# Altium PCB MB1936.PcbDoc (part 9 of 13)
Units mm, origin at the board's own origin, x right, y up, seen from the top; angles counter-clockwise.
Board outline 172 x 137 mm, 6 copper layers (Top Layer, Signal Layer 1, Signal Layer 2, Signal Layer 3, Signal Layer 4, Bottom Layer), stack 1.549 mm thick; 859 components, 672 nets, 3477 pads, 2222 vias.
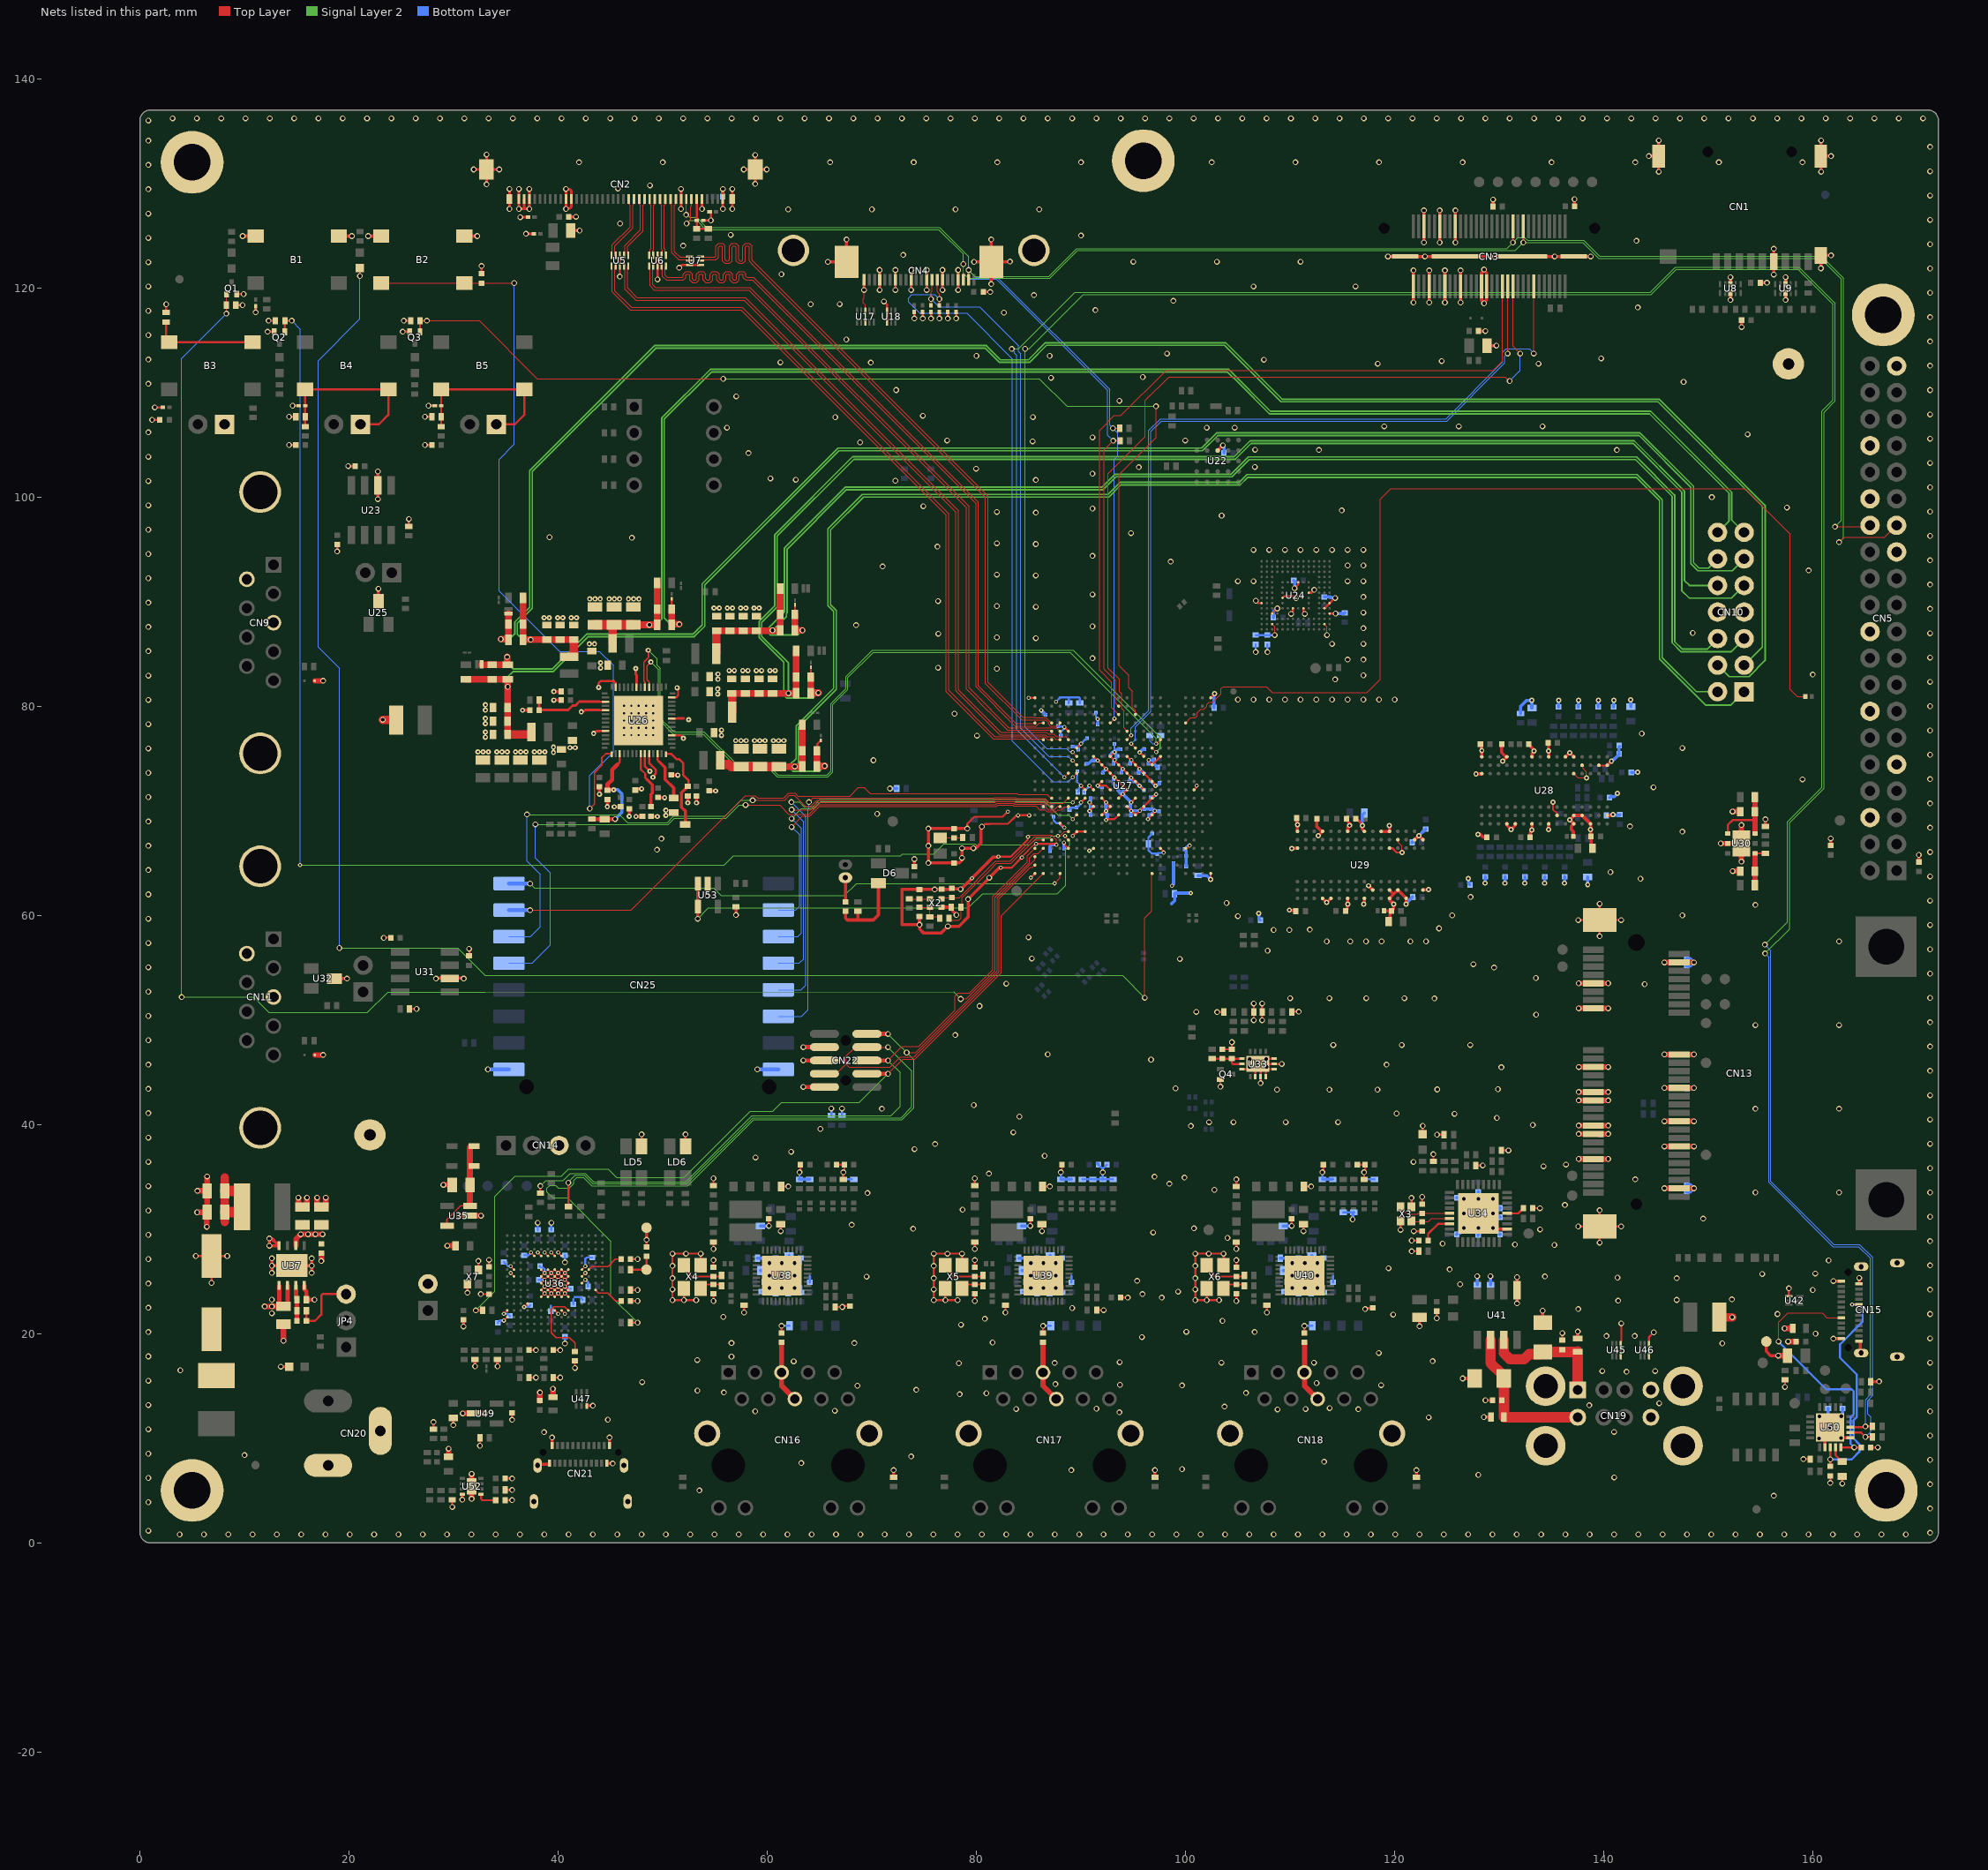
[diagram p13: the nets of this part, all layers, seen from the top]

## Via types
v1: diameter 0.55, hole 0.35, Top Layer to Bottom Layer, 1661 vias
v2: diameter 0.4, hole 0.2, Top Layer to Bottom Layer, tented both sides, 253 vias
v3: diameter 0.5, hole 0.2, Top Layer to Bottom Layer, 157 vias
v4: diameter 0.5, hole 0.25, Top Layer to Bottom Layer, 145 vias
v5: diameter 0.4, hole 0.2, Top Layer to Bottom Layer, 6 vias

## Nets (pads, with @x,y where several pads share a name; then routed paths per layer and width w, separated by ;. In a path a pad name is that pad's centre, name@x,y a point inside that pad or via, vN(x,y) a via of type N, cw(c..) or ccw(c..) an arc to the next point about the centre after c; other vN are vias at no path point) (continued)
GND: (continued)
  other v1: 3.8,0.8 6.125,0.8 8.45,0.8 10.775,0.8 13.1,0.8 15.425,0.8 17.75,0.8 20.075,0.8 22.4,0.8 24.725,0.8 27.05,0.8 29.375,0.8 31.7,0.8 34.025,0.8 36.35,0.8 38.675,0.8 41,0.8 43.325,0.8 45.65,0.8 47.975,0.8 50.3,0.8 52.625,0.8 54.95,0.8 57.275,0.8 59.6,0.8 61.925,0.8 64.25,0.8 66.575,0.8 68.9,0.8 71.225,0.8 73.55,0.8 75.875,0.8 78.2,0.8 80.525,0.8 82.85,0.8 85.175,0.8 87.5,0.8 89.825,0.8 92.15,0.8 94.475,0.8 96.8,0.8 99.125,0.8 101.45,0.8 103.775,0.8 106.1,0.8 108.425,0.8 110.75,0.8 113.075,0.8 115.4,0.8 117.725,0.8 120.05,0.8 122.375,0.8 124.7,0.8 127.025,0.8 129.35,0.8 131.675,0.8 134,0.8 136.325,0.8 138.65,0.8 140.975,0.8 143.3,0.8 145.625,0.8 147.95,0.8 150.275,0.8 152.6,0.8 154.925,0.8 157.25,0.8 159.575,0.8 161.9,0.8 164.225,0.8 166.55,0.8 168.875,0.8 171.2,0.95 0.8,1.15 171.2,3.275 0.8,3.875 156.25,4.5 53.5,5 171.2,5.6 0.8,6.2 141,6.25 128,6.5 89.075,6.95 99.66,7.05 63.25,7.625 113.25,7.75 171.2,7.925 73.75,8.25 10,8.375 0.8,8.525 160.587,9.988 171.2,10.25 38.65,10.58 140.975,10.6 0.8,10.85 44.75,11.775 123.25,12 160.612,12.087 93.675,12.475 58.85,12.575 171.2,12.575 66.45,12.625 108.8,12.75 116.525,12.775 83.8,12.8 111.475,12.8 91.475,12.825 113.775,12.875 103.725,13.025 138.6,13.15 0.8,13.175 145.3,13.35 78.4,14.2 80.95,14.3 105.775,14.325 55.85,14.375 53.325,14.55 74.25,14.625 171.2,14.9 68.625,15.025 99.66,15.05 118.7,15.075 93.725,15.1 87.55,15.175 112.525,15.275 48.03,15.376 0.8,15.5 142.175,16.35 139.85,16.425 144.9,16.425 3.875,16.5 78.325,17.175 87.475,17.2 103.425,17.225 112.275,17.225 171.2,17.225 93.7,17.275 62.525,17.35 123.625,17.375 53.3,17.475 56.575,17.8 0.8,17.825 118.475,18.15 151.325,19.075 56.575,19.1 68.325,19.1 81.55,19.15 171.2,19.55 95.825,19.675 140.25,19.775 142.95,19.775 160.25,20 0.8,20.15 106.6,20.15 100.075,20.175 78.525,20.85 103.525,21.225 80.8,21.425 55.8,21.6 119.85,21.825 156.6,21.875 171.2,21.875 137.55,22.35 89.15,22.45 0.8,22.475 141.375,23.15 146.975,23.225 152.25,23.275 97.725,23.45 95.875,23.775 99.275,24.025 159.975,24.175 171.2,24.2 61.4,24.35 62.6,24.35 86.4,24.35 87.6,24.35 111.4,24.35 112.6,24.35 126.25,24.725 0.8,24.8 95.375,25.05 146.975,25.3 141.3,25.35 69.5,25.45 134.375,25.475 60.2,25.55 61.4,25.55 62.6,25.55 85.2,25.55 86.4,25.55 87.6,25.55 110.2,25.55 111.4,25.55 112.6,25.55 155.15,25.7 160.225,25.75 125.25,26.15 119.4,26.25 171.2,26.525 60.2,26.75 61.4,26.75 62.6,26.75 85.2,26.75 86.4,26.75 87.6,26.75 110.2,26.75 111.4,26.75 112.6,26.75 161.5,27 0.8,27.125 135.275,28.475 131.5,28.525 124.575,28.6 171.2,28.85 104,29.15 0.8,29.45 96.9,29.675 133.9,29.975 73.95,30.025 100.8,30.075 68.075,30.4 149.5,31 171.2,31.175 126.6,31.5 128,31.5 0.8,31.775 78.675,31.85 136.275,32.3 129.4,32.9 69.575,33.45 154.5,33.5 162.5,33.5 171.2,33.5 102.75,33.75 0.8,34.1 98.45,34.325 143,34.75 99.9,34.925 97.025,35 81.2,35.3 171.2,35.825 134.225,36 136.375,36.175 0.8,36.425 121.8,36.425 58.875,36.85 86.525,37 62.275,37.4 74.075,37.65 76.05,38.125 171.2,38.15 0.8,38.75 83.525,39.25 65.075,39.575 100.5,39.85 133.2,39.95 102.25,40.225 104.575,40.225 109.575,40.225 114.575,40.225 171.2,40.475 129.775,40.625 84.1,40.75 125.725,41.025 120.175,41.05 0.8,41.075 70.95,41.5 154.5,41.5 162.5,41.5 79.75,41.85 171.2,42.8 108.75,43.325 113.75,43.325 118.35,43.325 124.075,43.35 129.875,43.375 0.8,43.4 99.044,43.453 171.2,45.125 59.04,45.265 130.2,45.475 106.125,45.49 107.75,45.49 0.8,45.725 119.225,45.725 106.925,45.815 96.7,46.2 106.125,46.24 107.725,46.265 86.825,46.7 171.2,47.45 114.125,47.6 120.675,47.6 127.225,47.6 0.8,48.05 77.975,48.55 154.5,49.5 162.5,49.5 171.2,49.775 0.8,50.375 133.525,50.5 101.03,50.765 80.3,51.325 123.8,52.05 110,52.075 113.75,52.075 117.275,52.075 120.925,52.075 171.2,52.1 0.8,52.7 143.909,53.412 82.85,53.475 28.315,53.95 30.965,53.95 133.5,54 171.2,54.425 129.5,55 0.8,55.025 127.525,55.325 99.45,55.825 85.3,55.875 107.85,56.625 171.2,56.75 31.475,56.795 0.8,57.35 113.5,57.5 115.75,57.5 117.25,57.5 118.75,57.5 121.5,57.5 123,57.5 162.5,57.5 23.315,57.845 84.975,57.9 108.427,58.602 109.927,58.602 111.875,58.625 124.25,58.75 171.2,59.075 0.8,59.675 105,59.925 125.5,60 147.5,60 154.5,61 103.925,61.175 171.2,61.4 127.25,61.75 0.8,62 143.5,63.5 171.2,63.725 140.625,64.125 0.8,64.325 171.2,66.05 49.45,66.275 0.8,66.65 49.875,67.325 147.5,68 171.2,68.375 142.5,68.5 0.8,68.975 70.5,69.7 171.2,70.7 0.8,71.3 144.75,72.25 159,73 171.2,73.025 0.8,73.625 70.15,74.825 171.2,75.35 0.8,75.95 147.5,76 80.05,77.175 143.625,77.375 171.2,77.675 0.8,78.275 77.9,79.275 171.2,80 0.8,80.6 105,80.625 106.5,80.625 108,80.625 109.5,80.625 111,80.625 112.5,80.625 114,80.625 115.5,80.625 117,80.625 118.5,80.625 120,80.625 171.2,82.325 114.3,82.55 0.8,82.925 117,82.95 159.975,83.025 81.95,83.575 76.325,83.675 115.5,84.45 117,84.45 91.1,84.575 171.2,84.65 0.8,85.25 114,85.95 117,85.95 85.675,86.5 81.95,86.575 76.35,86.925 171.2,86.975 148.5,87 117,87.45 0.8,87.575 91.1,87.625 68.5,87.75 117,88.95 171.2,89.3 85.675,89.5 81.95,89.575 0.8,89.9 76.325,90.05 117,90.45 91.1,90.675 171.2,91.625 105,91.95 106.5,91.95 115.5,91.95 117,91.95 0.8,92.225 85.675,92.5 81.95,92.575 159.587,92.982 71.025,93.35 115.5,93.45 117,93.45 98.575,93.825 171.2,93.95 91.1,94.375 0.8,94.55 106.5,94.95 108,94.95 109.5,94.95 111,94.95 112.5,94.95 114,94.95 115.5,94.95 117,94.95 76.275,95.25 85.675,95.5 81.95,95.575 47.05,96.1 39.175,96.15 171.2,96.275 94.775,96.55 0.8,96.875 103.45,98.225 85.675,98.5 81.95,98.575 171.2,98.6 114.936,98.709 91.1,98.9 157.5,99 74.925,99.125 0.8,99.2 150.325,99.975 171.2,100.925 0.8,101.525 72.25,101.55 85.675,101.625 62.725,101.65 60.3,101.775 91.1,102.225 79.975,102.7 95.525,102.85 106.625,102.875 171.2,103.25 0.8,103.85 58.2,104.2 112.75,104.5 141.25,104.5 106.65,104.525 68.875,105.225 85.375,105.325 77.2,105.4 99.975,105.4 171.2,105.575 91.1,105.7 153.75,106 0.8,106.175 56.15,106.625 102.025,106.625 104.7,106.625 119,106.75 126.125,106.75 134.125,106.75 66.5,107.625 85.4,107.65 74.875,107.775 171.2,107.9 93.675,109.2 57.025,109.625 72.325,110.225 171.2,110.225 0.8,110.825 147.625,111 87.125,111.4 95.9,111.475 171.2,112.55 118.375,112.75 133.75,112.75 69.9,112.85 61.25,112.875 124.5,113 107.5,113.125 0.8,113.15 139.75,113.25 80,113.5 87,113.5 98.225,113.725 171.2,114.875 67.55,115.05 0.8,115.475 171.2,117.2 82.625,117.625 0.8,117.8 91.375,117.875 143.25,118.125 64.15,118.425 66.925,118.45 98.825,118.75 85.501,119.298 171.2,119.525 0.8,120.125 106.5,120.125 116.25,120.125 81.425,120.355 61.35,121.3 171.2,121.85 0.8,122.45 83.2,122.505 95,122.5 103,122.5 111,122.5 73,123.15 51.95,124.025 171.2,124.175 143.125,124.5 81.415,124.625 0.8,124.775 90,125 56.5,125.075 45.925,126.15 171.2,126.5 0.8,127.1 62,127.5 70,127.5 78,127.5 86,127.5 171.2,128.825 0.8,129.425 45.725,129.5 48.775,129.8 171.2,131.15 0.8,131.75 42,132 50,132 66,132 74,132 82,132 90,132 102.5,132 110.5,132 118.5,132 126.5,132 135,132 143,132 151,132 159,132 171.2,133.475 0.8,134.075 0.8,136 3.125,136.2 5.45,136.2 7.775,136.2 10.1,136.2 12.425,136.2 14.75,136.2 17.075,136.2 19.4,136.2 21.725,136.2 24.05,136.2 26.375,136.2 28.7,136.2 31.025,136.2 33.35,136.2 35.675,136.2 38,136.2 40.325,136.2 42.65,136.2 44.975,136.2 47.3,136.2 49.625,136.2 51.95,136.2 54.275,136.2 56.6,136.2 58.925,136.2 61.25,136.2 63.575,136.2 65.9,136.2 68.225,136.2 70.55,136.2 72.875,136.2 75.2,136.2 77.525,136.2 79.85,136.2 82.175,136.2 84.5,136.2 86.825,136.2 89.15,136.2 91.475,136.2 93.8,136.2 96.125,136.2 98.45,136.2 100.775,136.2 103.1,136.2 105.425,136.2 107.75,136.2 110.075,136.2 112.4,136.2 114.725,136.2 117.05,136.2 119.375,136.2 121.7,136.2 124.025,136.2 126.35,136.2 128.675,136.2 131,136.2 133.325,136.2 135.65,136.2 137.975,136.2 140.3,136.2 142.625,136.2 144.95,136.2 147.275,136.2 149.6,136.2 151.925,136.2 154.25,136.2 156.575,136.2 158.9,136.2 161.225,136.2 163.55,136.2 165.875,136.2 168.2,136.2 170.525,136.2
  other v2: 95.6,75.575
  other v3: 46.8,69.467 50.3,69.552 50.3,70.052 44.7,70.382 43.95,71.587 39.55,75.577 32.324,75.625 32.825,75.625 33.326,75.625 34.124,75.625 34.625,75.625 35.126,75.625 35.924,75.625 36.425,75.625 36.926,75.625 37.724,75.625 38.225,75.625 38.726,75.625 41.124,76.029 41.625,76.029 39.55,76.077 56.979,76.702 57.48,76.702 57.981,76.702 58.779,76.702 59.28,76.702 59.781,76.702 60.579,76.702 61.08,76.702 61.581,76.702 33.05,77.027 55.62,77.202 46.3,77.227 47,77.227 47.7,77.227 48.4,77.227 49.1,77.227 33.05,77.527 55.62,77.702 46.3,77.927 47,77.927 47.7,77.927 48.4,77.927 49.1,77.927 33.05,78.327 46.3,78.627 47,78.627 47.7,78.627 48.4,78.627 49.1,78.627 52.48,78.702 33.05,78.827 46.3,79.327 47,79.327 47.7,79.327 48.4,79.327 49.1,79.327 33.05,79.627 46.3,80.027 47,80.027 47.7,80.027 48.4,80.027 49.1,80.027 33.05,80.127 55.25,81.152 55.25,81.652 55.275,82.577 55.275,83.077 56.35,83.402 56.85,83.402 57.65,83.402 58.15,83.402 58.95,83.402 59.45,83.402 60.25,83.402 60.75,83.402 44.05,83.65 44.05,84.15 42.975,85.95 43.476,85.95 38.65,88.45 39.151,88.45 39.95,88.45 40.451,88.45 41.25,88.45 41.751,88.45 54.9,89.377 55.4,89.377 56.175,89.377 56.675,89.377 57.45,89.377 57.95,89.377 58.725,89.377 59.225,89.377 43.024,90.252 43.525,90.252 44.026,90.252 44.874,90.252 45.375,90.252 45.876,90.252 46.724,90.252 47.225,90.252 47.726,90.252
  other v4: 123.25,62.475 110.15,66.4 138.325,73.15 127.775,73.525 133.325,75.725 128.325,75.75 102.775,81.2
GPIO.SDMMC3_CK: R94.1 U27.D19 | length 96.6
  Top Layer w0.1: U27.D19@100,78.4 100.49,78.89 100.928,78.89 101.11,79.072 101.11,79.375 101.425,79.69 101.728,79.69 102.038,80 102.038,80.157 102.25,80.369 102.591,80.369 103.4,81.178 103.4,81.675 103.578,81.853 107.747,81.853 108.3,81.3 117.369,81.3 118.625,82.556 118.625,99.8 119.625,100.8 153.488,100.8 157.825,96.463 157.825,81.6 158.5,80.925 R94.1@159.275,80.925
HDMI_CEC: CN3.47 U27.F12 | length 77.6
  Top Layer w0.1: U27.F12@94.4,76.8 v2@94.8,77.2 ; v1(133.3,113.725) CN3.47@133.3,120.13
  Bottom Layer w0.1: v2(94.8,77.2) 94.8,77.881 96.486,79.567 96.486,106.343 97.612,107.47 124.887,107.47 130.315,112.898 130.315,113.841 130.624,114.15 132.875,114.15 v1(133.3,113.725)
HDMI_I2S2.CK: CN3.35 U27.C11 | length 76.3
  Top Layer w0.09: 91.77,84.475 91.77,83.435 92.925,82.279 92.925,79.875 U27.C11@93.6,79.2
  Top Layer w0.1: 91.77,84.475 91.77,106.37 93.19,107.79 93.82,107.79 98.145,112.115 129.438,112.115 130.3,112.977 CN3.35@130.3,120.13
HDMI_I2S2.WS: CN3.37 U27.G13 | length 75.2
  Top Layer w0.1: v2(94.8,76.4) U27.G13@95.2,76 ; v1(130.8,113.725) CN3.37@130.8,120.13
  Bottom Layer w0.1: v2(94.8,76.4) 95.2,76.8 95.2,78.012 96.686,79.498 96.686,106.261 97.695,107.27 124.97,107.27 129.975,112.275 130.515,112.815 130.515,113.44 v1(130.8,113.725)
HDMI_I2S2_SDO: CN3.39 U27.E12 | length 79.6
  Top Layer w0.09: 92.605,84.475 92.6,84.47 92.6,83.643 93.665,82.578 93.665,81.388 93.885,81.168 93.885,79.765 94.09,79.56 94.09,77.91 U27.E12@94.4,77.6
  Top Layer w0.1: 92.605,84.475 92.605,102.247 96.13,105.772 96.13,109.216 98.404,111.49 130.567,111.49 130.972,111.085 v1(131,111.085) ; CN3.39@131.3,120.13 131.3,114.429 v1(132.004,113.725)
  Bottom Layer w0.1: v1(131,111.085) 132.004,112.089 v1(132.004,113.725)
HSE_IN: C90.2 U27.V3 X2.3 | length 13.1
  Top Layer w0.1: X2.3@76.648,61.576 76.772,61.7 C90.2@77.65,61.7 78.35,61.7 81.825,65.175 83.225,65.175 85.56,67.51 86.89,67.51 U27.V3@87.2,67.2
HSE_OUT: R72.1 R75.2 U27.V2 | length 13.4
  Top Layer w0.1: R75.2@77.375,59.725 77.575,59.525 78.325,59.525 78.55,59.75 78.55,60.725 R72.1@78.5,60.775 78.615,60.889 78.615,61.664 81.3,64.35 81.925,64.975 83.275,64.975 83.285,64.985 83.304,64.985 85.519,67.2 U27.V2@86.4,67.2
I2C1.SCL: R224.1 U27.K5 U50.18 | length 245.2
  Top Layer w0.1: v2(88.4,73.2) U27.K5@88.8,73.6
  Top Layer w0.2: U50.18@163.575,11.05 164.945,11.05 v1(165.02,11.125) R224.1@165.695,11.125
  Signal Layer 2 w0.1: v1(83.375,114.15) 84.024,114.15 89.424,119.55 144.425,119.55 146.85,121.975 158.675,121.975 162.125,118.525 162.125,109.175 161.05,108.1 161.05,72.13 157.775,68.855 157.775,58.7 v1(155.425,56.35)
  Bottom Layer w0.1: v1(83.375,114.15) 83.375,114.132 83.625,113.882 83.625,113.75 83.85,113.525 83.85,84.475 83.85,77.749 v2(88.4,73.2) ; v1(155.425,56.35) 155.775,56 155.775,34.475 161.925,28.325 164.375,28.325 165.5,27.2 165.5,14.167 165.02,13.687 v1(165.02,11.125)
I2C1.SDA: R228.1 U27.H6 U50.17 | length 243.6
  Top Layer w0.1: v2(89.2,75.6) U27.H6@89.6,75.2
  Top Layer w0.2: U50.17@163.575,10.55 164.595,10.55 v1(165.02,10.125) R228.1@165.695,10.125
  Signal Layer 2 w0.1: v1(84.65,114.175) 85.05,114.175 90.225,119.35 144.508,119.35 146.933,121.775 158.592,121.775 161.925,118.442 161.925,109.275 160.85,108.2 160.85,72.213 157.575,68.938 157.575,59.375 v1(155.4,57.2)
  Bottom Layer w0.1: v1@84.65,114.175 84.65,78.024 86.724,75.95 88.617,75.95 88.936,75.631 89.169,75.631 v2(89.2,75.6) ; v1(155.4,57.2) 155.975,56.625 155.975,34.558 162.008,28.525 164.458,28.525 165.7,27.283 165.7,14.076 165.22,13.596 165.22,12.338 165.545,12.013 165.545,10.65 v1(165.02,10.125)
I2C2.SCL: CN2.7 CN3.44 CN4.20 CN5.28 R32.1 U27.B11 | length 201
  Top Layer w0.09: 92.19,84.475 92.19,83.524 93.29,82.424 93.29,80.31 U27.B11@93.6,80
  Top Layer w0.1: v1(52.274,126.153) 52.667,126.546 52.667,127.768 52.75,127.851 CN2.7@52.75,128.5 ; v1(78.746,122.268) 78.746,120.754 CN4.20@78.75,120.75 ; 92.19,84.475 92.19,104.49 v1(93.075,105.375) ; v1@93.145,105.375 R32.1@93.73,105.375 ; v1(162.1,97.15) 162.114,97.164 165.329,97.164 CN5.28@165.455,97.29
  Top Layer w0.15: v1(132.3,124.34) CN3.44@132.3,125.87
  Signal Layer 2 w0.1: v1(52.274,126.153) 52.28,126.153 52.577,126.45 53.25,126.45 54.125,125.575 76.392,125.575 78.746,123.221 v1(78.746,122.268) 78.746,121.4 79.246,120.9 87,120.9 89.665,123.565 131.525,123.565 v1(132.3,124.34) 138.005,124.34 139.52,122.825 160.725,122.825 162.7,120.85 162.7,97.75 v1(162.1,97.15)
  Bottom Layer w0.1: v1(78.746,122.268) 78.746,121.4 79.321,120.825 81.917,120.825 92.545,110.197 92.545,105.905 v1(93.075,105.375)
I2C2.SDA: CN2.8 CN3.40 CN4.21 CN5.27 R31.1 U27.D10 | length 204
  Top Layer w0.1: v1(52.242,126.977) 52.246,126.982 52.246,128.496 CN2.8@52.25,128.5 ; CN4.21@79.25,120.75 v1(79.25,121.7) ; U27.D10@92.8,78.4 v2@93.2,78.8 ; v1(93.05,106.575) R31.1@93.705,106.575 ; v1(131.3,124.34) CN3.40@131.3,125.87 ; v1(162.5,95.675) 162.966,96.141 166.846,96.141 CN5.27@167.995,97.29
  Signal Layer 2 w0.1: v1(52.242,126.977) 52.338,126.977 52.59,126.725 53.258,126.725 54.208,125.775 76.475,125.775 79.25,123 v1(79.25,121.7) 79.85,121.1 86.917,121.1 89.582,123.765 130.725,123.765 v1(131.3,124.34) 131.766,124.806 132.435,124.806 132.701,124.54 138.088,124.54 139.603,123.025 160.808,123.025 162.9,120.933 162.9,96.075 v1(162.5,95.675)
  Bottom Layer w0.1: v1(79.25,121.7) 79.925,121.025 82,121.025 92.75,110.275 92.75,106.875 v1(93.05,106.575) 93.5,106.125 93.5,103.89 93.19,103.58 93.19,78.81 v2(93.2,78.8)
I2C7.SCL: R261.1 U26.33 U27.F16 | length 73.5
  Top Layer w0.09: v2@97.2,76.4 U27.F16@97.6,76.8
  Top Layer w0.15: U26.33@48.7,81.797 48.7,82.327 48.503,82.525 48.503,83.858 v3(48.865,84.22)
  Signal Layer 2 w0.1: v3(48.865,84.22) 49.575,83.511 49.575,81.55 49.575,78.75 50.975,77.35 53.875,77.35 56.75,74.475 59.7,74.475 60.95,73.225 62.125,73.225 65.775,73.225 66.275,73.725 66.275,80.175 67.712,81.612 67.712,82.738 70.127,85.152 88.973,85.152 97.2,76.925 v2(97.2,76.4)
  Bottom Layer w0.09: R261.1@96.575,77.175 96.575,76.655 96.83,76.4 v2(97.2,76.4)
I2C7.SDA: R260.1 U26.34 U27.G15 | length 77.8
  Top Layer w0.09: U27.G15@96.8,76 v2(97.2,75.6)
  Top Layer w0.15: U26.34@48.3,81.797 48.3,82.302 48.2,82.402 48.2,84.227 48.65,84.677 v3@48.65,85.302 ; v3@48.5,85.452 v3@48.65,85.302 ; v3(48.619,85.352) 48.65,85.321 v3@48.65,85.302
  Signal Layer 2 w0.1: v3(48.619,85.352) 49.45,84.521 49.45,83.918 49.716,83.652 49.775,83.593 49.775,81.633 49.775,78.833 50.654,77.954 51.058,77.55 53.958,77.55 54.491,77.016 56.833,74.675 59.783,74.675 61.033,73.425 62.208,73.425 65.692,73.425 66.075,73.808 66.075,80.258 67.512,81.695 67.512,82.82 67.571,82.879 70.044,85.352 70.475,85.352 89.248,85.352 97.575,77.025 97.575,75.975 v2(97.2,75.6)
  Bottom Layer w0.09: v2(97.2,75.6) 97.6,76 R260.1@97.6,77.175
I_SENS_1V8_N: C19.1 CN10.14 LNK3.1 R41.2 | length 136.6
  Top Layer w0.2: C19.1@50.855,89.277 LNK3.1@50.855,90.275
  Top Layer w0.64: R41.2@50.855,87.827 C19.1@50.855,89.277 ; R41.2@50.857,87.829 v1(51.585,87.829)
  Signal Layer 2 w0.15: v1(51.585,87.829) 50.746,87.829 50.15,88.425 50.15,107.45 54.65,111.95 104.025,111.95 105.1,110.875 108.025,107.95 144.375,107.95 151.975,100.35 151.975,97.715 CN10.14@150.88,96.62
I_SENS_1V8_P: C16.2 C17.2 C18.2 C19.2 CN10.13 L1.2 R35.1 R41.1 | length 145.9
  Top Layer w0.64: C18.2@47.2,87.777 R41.1@49.455,87.777 C19.2@49.455,89.277 R35.1@49.455,91.777
  Top Layer w0.8: L1.2@45.195,86.002 45.195,87.727 45.245,87.777 C17.2@45.35,87.777
  Top Layer w0.9: C16.2@43.5,87.777 C17.2@45.35,87.777 C18.2@47.2,87.777
  Signal Layer 2 w0.15: v1(48.725,87.775) 49.348,87.775 49.9,88.327 49.9,107.554 54.546,112.2 104.129,112.2 104.277,112.052 108.129,108.2 144.479,108.2 152.225,100.454 152.225,97.815 CN10.13@153.42,96.62
I_SENS_VDD_DDR_N: C31.1 CN10.12 LNK9.1 R48.2 | length 141.4
  Top Layer w0.64: LNK9.1@32.677,83.977 C31.1@33.675,83.977 R48.2@35.125,83.977 ; R48.2@35.123,83.979 v1(35.123,84.707)
  Signal Layer 2 w0.15: v1(35.123,84.707) 35.123,84.127 35.7,83.55 39.421,83.55 42.771,86.9 52.921,86.9 53.775,87.754 53.775,91.7 66.75,104.675 101.521,104.675 102.971,106.125 143.479,106.125 148.575,101.029 148.575,93.729 149.099,93.205 150.005,93.205 CN10.12@150.88,94.08
I_SENS_VDD_DDR_P: C31.2 C41.2 C44.2 C47.2 CN10.11 L5.2 R47.1 R48.1 | length 151.8
  Top Layer w0.64: R47.1@31.175,82.577 C31.2@33.675,82.577 R48.1@35.175,82.577 35.175,81.847 C41.2@35.175,80.322 ; C47.2@35.175,77.277 C44.2@35.175,78.577 C41.2@35.175,79.877
  Top Layer w0.8: C47.2@35.4,77.277 L5.2@37.175,77.277
  Signal Layer 2 w0.15: v1(35.177,81.847) 35.177,82.802 35.675,83.3 39.525,83.3 42.875,86.65 53.025,86.65 54.025,87.65 54.025,91.596 66.854,104.425 101.625,104.425 103.075,105.875 143.375,105.875 148.325,100.925 148.325,93.625 148.995,92.955 152.295,92.955 CN10.11@153.42,94.08
I_SENS_VDDCORE_N: C20.1 CN10.6 LNK5.2 R42.2 | length 124.5
  Top Layer w0.2: C20.1@62.63,88.752 62.65,88.772 LNK5.2@62.65,89.7
  Top Layer w0.64: R42.2@62.63,87.252 C20.1@62.63,88.752 ; R42.2@62.632,87.254 v1@63.325,87.254
  Signal Layer 2 w0.15: v1(63.36,87.254) 62.906,86.8 60.314,86.8 60.05,87.064 60.05,87.436 61.65,89.036 61.65,95.129 67.471,100.95 92.025,100.95 93.25,102.175 104.346,102.175 105.996,103.825 143.129,103.825 146.775,100.179 146.775,86.179 147.504,85.45 149.87,85.45 CN10.6@150.88,86.46
I_SENS_VDDCORE_P: C20.2 C21.2 C22.2 C23.2 C24.2 CN10.5 L2.2 R36.1 R42.1 | length 131.9
  Top Layer w0.2: C24.2@58.975,87.202 C24.2@59.023,87.25 ; R42.1@61.228,87.25 R42.1@61.23,87.252
  Top Layer w0.64: C21.2@55.15,87.202 C22.2@56.425,87.202 C23.2@57.7,87.202 C24.2@58.975,87.202 60.5,87.202 61.23,87.202 R42.1@61.23,87.252 C20.2@61.23,88.752 R36.1@61.23,91.252
  Top Layer w0.8: L2.2@55.115,85.027 C21.2@55.115,87
  Signal Layer 2 w0.15: v1(60.5,87.25) 61.825,88.575 61.825,88.858 61.9,88.933 61.9,95.025 67.575,100.7 92.129,100.7 93.354,101.925 104.45,101.925 106.1,103.575 143.025,103.575 146.525,100.075 146.525,86.075 147.4,85.2 152.16,85.2 CN10.5@153.42,86.46
I_SENS_VDDCPU_N: C25.1 CN10.4 LNK6.2 R43.2 | length 172.2
  Top Layer w0.64: v1(34.515,86.404) R43.2@35.243,86.404 ; R43.2@35.245,86.402 C25.1@35.245,87.852 LNK6.2@35.245,88.85
  Signal Layer 2 w0.15: v1(34.515,86.404) 35.354,86.404 35.85,86.9 35.85,88.029 37.275,89.454 37.275,102.529 49.221,114.475 80.951,114.475 82.304,113.122 84.968,113.122 86.596,114.75 103.829,114.75 109.229,109.35 145.279,109.35 155.425,99.204 155.425,84.369 153.876,82.82 151.98,82.82 CN10.4@150.88,83.92
I_SENS_VDDCPU_P: C25.2 C26.2 C27.2 C28.2 CN10.3 L3.2 R39.1 R43.1 | length 174.3
  Top Layer w0.64: R39.1@36.645,90.352 C25.2@36.645,87.852 R43.1@36.645,86.352 C26.2@38.9,86.352 C27.2@40.2,86.352 C28.2@41.5,86.352
  Top Layer w0.8: L3.2@41.05,84.702 41.5,84.702 41.5,86
  Signal Layer 2 w0.15: v1(37.375,86.35) 36.625,86.35 36.1,86.875 36.1,87.925 37.525,89.35 37.525,102.425 49.325,114.225 80.847,114.225 82.201,112.872 85.072,112.872 86.7,114.5 103.725,114.5 109.125,109.1 145.175,109.1 155.15,99.125 155.15,85.65 CN10.3@153.42,83.92
I_SENS_VDDGPU_N: C33.1 CN10.10 LNK10.2 R51.2 | length 128.4
  Top Layer w0.2: C33.1@64.175,82.797 LNK10.2@64.175,83.725
  Top Layer w0.64: R51.2@64.155,81.277 C33.1@64.155,82.777 ; R51.2@64.157,81.279 v1(64.885,81.279)
  Signal Layer 2 w0.15: v1(64.885,81.279) 64.381,80.775 61.839,80.775 61.575,81.039 61.575,84.221 59.223,86.574 59.223,88.101 60.7,89.579 60.7,96.379 68.171,103.85 104.646,103.85 106.171,105.375 142.904,105.375 147.7,100.579 147.7,92.025 148.185,91.54 CN10.10@150.88,91.54
I_SENS_VDDGPU_P: C33.2 C34.2 C35.2 C36.2 C37.2 CN10.9 L4.2 R45.1 R51.1 | length 136.6
  Top Layer w0.64: C34.2@56.6,81.227 C35.2@57.9,81.227 C36.2@59.2,81.227 C37.2@60.5,81.227 R51.1@62.755,81.227 ; R51.1@62.755,81.277 C33.2@62.755,82.777 R45.1@62.755,85.277
  Top Layer w0.8: L4.2@56.625,79.427 56.625,80.9
  Signal Layer 2 w0.15: v1(62.025,81.225) 62.025,84.125 59.473,86.677 59.473,87.998 60.95,89.475 60.95,96.275 68.275,103.6 104.75,103.6 106.275,105.125 142.8,105.125 147.45,100.475 147.45,91.05 148.175,90.325 152.205,90.325 CN10.9@153.42,91.54
I_SENS_VDDIO_N: C55.1 CN10.2 LNK12.1 R54.2 | length 136.5
  Top Layer w0.2: C55.1@64.775,75.797 64.775,76.375 LNK12.1@65.125,76.725
  Top Layer w0.64: R54.2@64.755,74.277 C55.1@64.755,75.727 C55.1@64.755,75.777 ; R54.2@64.757,74.279 v1(65.485,74.279)
  Signal Layer 2 w0.15: v1(65.485,74.279) 64.981,73.775 62.439,73.775 62.175,74.039 62.175,74.411 62.75,74.986 62.75,78.104 65.8,81.154 66.35,81.704 66.35,89.059 65.8,89.609 65.8,90.15 65.8,96.954 69.096,100.25 92.571,100.25 93.721,101.4 105.121,101.4 105.871,102.15 143.175,102.15 145.575,99.75 145.575,84.65 148.845,81.38 CN10.2@150.88,81.38
I_SENS_VDDIO_P: C52.2 C53.2 C54.2 C55.2 CN10.1 L6.2 R53.1 R54.1 | length 144.3
  Top Layer w0.64: C54.2@61.1,74.227 R54.1@63.355,74.227 C55.2@63.355,75.727 R53.1@63.355,78.227
  Top Layer w0.9: L6.2@55.55,74.427 56.35,74.427 56.55,74.227 C52.2@57.5,74.227 C53.2@59.3,74.227 C54.2@61.1,74.227
  Signal Layer 2 w0.15: v1(62.625,74.225) 63,74.6 63,78 66.05,81.05 66.6,81.6 66.6,89.163 66.05,89.713 66.05,96.85 69.2,100 92.675,100 93.825,101.15 105.225,101.15 105.95,101.875 143.097,101.875 145.325,99.647 145.325,84.511 149.741,80.095 152.135,80.095 CN10.1@153.42,81.38
IMU_INT1: CN4.14 U13.1 U27.J6 | length 56.2
  Top Layer w0.1: U13.1@75.66,118.312 v1(75.66,118.937) 75.66,119.55 75.75,119.64 CN4.14@75.75,120.75 ; v2(89.2,74.8) U27.J6@89.6,74.4
  Bottom Layer w0.1: v1(75.66,118.937) 76.422,118.175 80.325,118.175 84.025,114.475 84.025,113.916 84.25,113.691 84.25,77.887 86.937,75.2 88.8,75.2 v2(89.2,74.8)
IMU_INT2: CN4.15 U14.1 U27.K6 | length 63
  Top Layer w0.1: CN4.15@76.25,120.75 76.25,119.595 76.46,119.385 v1(76.46,118.937) U14.1@76.46,118.312 ; v2(89.2,73.2) U27.K6@89.6,73.6
  Bottom Layer w0.1: v1(76.46,118.937) 76.431,118.937 76.006,119.362 73.825,119.362 73.5,119.037 73.5,118.65 74.575,117.575 79.066,117.575 83.45,113.191 83.45,76.67 87.321,72.799 88.8,72.799 v2(89.2,73.2)
JTCK_SWCLK: CN22.4 CN22.7 R153.2 U27.AA1 | length 83.4
  Top Layer w0.1: CN22.7@65.465,44.855 66.605,44.855 67.525,45.775 ; v1(71.55,47.39) 71.545,47.395 CN22.4@69.535,47.395 68.395,47.395 67.525,46.525 67.525,45.775 ; U27.AA1@85.6,64.8 85.596,64.8 85.386,64.59 85.166,64.59 82.175,61.599 82.175,54.583 74.042,46.45 72.7,46.45 71.75,45.5 67.8,45.5 67.525,45.775
  Top Layer w0.2: R153.2@40.975,32.15 40.975,33.45 v1(40.975,34.425)
  Signal Layer 2 w0.1: v1(40.975,34.425) 40.975,34.5 41.6,35.125 42.508,35.125 43.308,34.325 52.301,34.325 58.626,40.65 72.801,40.65 73.825,41.674 73.825,45.115 v1(71.55,47.39)
JTDI: CN22.8 R207.2 U27.AB2 | length 83.4
  Top Layer w0.1: v1(71.55,44.85) 72.95,46.25 74.125,46.25 82.375,54.5 82.375,59.967 86.4,63.992 U27.AB2@86.4,64
  Top Layer w0.3: v1(32.13,22.225) R207.2@32.775,22.225
  Top Layer w0.4: CN22.8@69.535,44.855 71.545,44.855 v1(71.55,44.85)
  Signal Layer 2 w0.1: v1(32.13,22.225) 33.95,24.045 33.95,33.1 35.895,35.045 40.304,35.045 40.984,35.725 44.783,35.725 45.583,34.925 48.867,34.925 52.053,34.925 58.378,41.25 60.525,41.25 61.375,42.1 68.8,42.1 v1(71.55,44.85)
JTDO_SWDO: CN22.6 R129.2 U27.W1 | length 73.5
  Top Layer w0.1: v1(71.55,46.12) 72.88,47.45 74.491,47.45 77.95,50.909 77.95,52.275 78.25,52.575 79.333,52.575 81.575,54.817 81.575,61.805 84.873,65.103 84.873,65.673 U27.W1@85.6,66.4
  Top Layer w0.2: R129.2@38.3,33.45 v1(38.3,34.125)
  Top Layer w0.4: CN22.6@69.535,46.125 71.545,46.125 v1(71.55,46.12)
  Signal Layer 2 w0.1: v1(38.3,34.125) 38.82,34.645 40.47,34.645 41.15,35.325 42.591,35.325 43.391,34.525 52.219,34.525 58.544,40.85 71.825,40.85 72.7,41.725 72.7,44.97 v1(71.55,46.12)
JTMS_SWDIO: CN22.2 R209.2 U27.Y1 | length 91.7
  Top Layer w0.09: v1(73.325,46.875) 74.191,46.875 81.98,54.664 81.98,55.07 81.975,55.075 81.975,56.092
  Top Layer w0.1: 81.975,56.092 81.975,61.668 85.6,65.293 U27.Y1@85.6,65.6
  Top Layer w0.2: R209.2@46.925,21.05 v1(47.6,21.05)
  Top Layer w0.4: CN22.2@69.535,48.665 71.545,48.665 v1(71.55,48.66)
  Signal Layer 2 w0.1: v1(47.6,21.05) 45.05,23.6 45.05,28.825 40.9,32.975 39.499,32.975 38.925,33.549 38.925,33.901 39.197,34.173 39.777,34.173 40.025,33.925 41.076,33.925 41.475,34.324 41.475,34.624 41.776,34.925 42.425,34.925 43.225,34.125 52.384,34.125 58.709,40.45 72.884,40.45 74.025,41.591 74.025,46.185 v1(71.55,48.66)
LED1: LD1.2 U27.AB15 | length 158.6
  Top Layer w0.1: v1(96.1,52.125) 96.075,52.15 96.075,59.725 96.78,60.43 96.78,63.98 U27.AB15@96.8,64
  Top Layer w0.2: v1(21.047,121.125) LD1.2@21.047,121.775
  Signal Layer 2 w0.1: v1(19.075,56.875) 30.375,56.875 33,54.25 93.975,54.25 v1(96.1,52.125)
  Bottom Layer w0.1: v1(19.075,56.875) 19.075,83.625 17.05,85.65 17.05,113.025 21.047,117.022 v1(21.047,121.125)
LED2: Q3.1 R17.2 U27.C13 | length 106.4
  Top Layer w0.09: 93.64,84.475 93.64,83.876 94.565,82.951 94.565,81.76 94.915,81.41 94.915,79.882 95.2,79.597 U27.C13@95.2,79.2
  Top Layer w0.1: v1(27.438,116.85) 32.45,116.85 38,111.3 v1(55.775,111.3) ; 93.64,84.475 93.64,102.151 97.175,105.686 v1(97.175,108.675)
  Top Layer w0.2: Q3.1@26.787,115.8 R17.2@26.788,116.85 v1(27.438,116.85)
  Signal Layer 2 w0.1: v1(55.775,111.3) 86.025,111.3 88.65,108.675 v1(97.175,108.675)
LED3: Q2.1 R16.2 U27.U5 | length 129
  Top Layer w0.09: v2(87.793,67.6) 87.833,67.64 88.051,67.64 88.126,67.715 88.126,67.723 88.403,68 U27.U5@88.8,68
  Top Layer w0.2: Q2.1@13.863,115.8 R16.2@13.863,116.85 v1(14.513,116.85)
  Signal Layer 2 w0.1: v2(15.312,64.812) 15.325,64.825 55.899,64.825 56.774,65.7 72.748,65.7 72.921,65.873 75.923,65.873 76.9,66.85 79.871,66.85 79.971,66.75 85.121,66.75 85.747,67.376 86.97,67.376 87.193,67.6 v2(87.793,67.6)
  Bottom Layer w0.1: v1(14.513,116.85) 15.325,116.038 15.325,64.825 v2(15.312,64.812)
LED4: Q1.1 R8.2 U27.W2 | length 163.4
  Top Layer w0.1: Q1.1@8.273,119.4 R8.2@8.273,118.35 8.273,117.527 v1(8.275,117.525) ; v1(78.5,52) 79.041,52 81.775,54.734 81.775,61.737 85.063,65.025 85.063,65.473 85.48,65.89 85.89,65.89 U27.W2@86.4,66.4
  Signal Layer 2 w0.1: v1(4,52.175) 10.85,52.175 12.325,50.7 21.75,50.7 23.725,52.675 33.025,52.675 77.825,52.675 v1(78.5,52)
  Bottom Layer w0.1: v1(4,52.175) 4,113.25 v1(8.275,117.525)
LVDS1.CLK_N: U5.10 U27.F5 | length 72.2
  Top Layer w0.09: U5.10@46.7,122.075 46.645,122.02 46.645,121.737 46.625,121.717 46.625,121.643 46.625,119.979 47.529,119.075 57.9,119.075 78.3,98.675 78.3,81.554 82.334,77.52 86.693,77.52 86.898,77.315 87.427,77.315 87.437,77.305 87.657,77.085 88.515,77.085 U27.F5@88.8,76.8
LVDS1.CLK_P: U5.9 U27.F4 | length 71.7
  Top Layer w0.09: U5.9@46.3,122.075 46.355,122.02 46.355,121.737 46.375,121.717 46.375,121.539 46.375,119.875 47.425,118.825 57.796,118.825 78.05,98.571 78.05,81.45 82.23,77.27 86.59,77.27 86.775,77.085 87.332,77.085 87.342,77.075 87.575,76.842 87.59,76.827 87.973,76.827 U27.F4@88,76.8
LVDS1.CLKcon_N: CN2.16 U5.1 | length 6.1
  Top Layer w0.09: U5.1@46.7,123.125 46.645,123.18 46.645,123.463 46.625,123.483 46.625,123.557 46.625,123.94 48.125,125.44 48.125,127.88 48.25,128.005 CN2.16@48.25,128.5
LVDS1.CLKcon_P: CN2.17 U5.2 | length 6.1
  Top Layer w0.09: U5.2@46.3,123.125 46.355,123.18 46.355,123.463 46.375,123.483 46.375,123.661 46.375,123.807 46.375,124.044 47.875,125.544 47.875,127.88 47.75,128.005 CN2.17@47.75,128.5
LVDS1.D0_N: U7.6 U27.D3 | length 70.7
  Top Layer w0.09: U7.6@53.625,123 53.68,122.945 53.963,122.945 53.983,122.925 54.873,122.925 54.991,122.925 55.089,123.022 55.089,123.989 55.333,124.233 55.735,124.233 55.979,123.989 55.979,122.682 56.076,122.584 56.271,122.584 56.369,122.682 56.369,123.989 56.613,124.233 57.015,124.233 57.259,123.989 57.259,122.682 57.356,122.584 57.551,122.584 57.649,122.682 57.649,123.989 57.893,124.233 58.295,124.233 58.539,123.989 58.539,122.661 58.642,122.558 81.125,100.075 81.125,82.254 84.454,78.925 85.472,78.925 85.482,78.915 86.642,78.915 87.157,78.4 U27.D3@87.2,78.4
LVDS1.D0_P: U7.5 U27.D4 | length 71.7
  Top Layer w0.09: U7.5@53.625,122.6 53.68,122.655 53.963,122.655 53.983,122.675 54.873,122.675 55.095,122.675 55.339,122.919 55.339,123.885 55.436,123.983 55.631,123.983 55.729,123.885 55.729,122.578 55.973,122.334 56.375,122.334 56.619,122.578 56.619,123.885 56.716,123.983 56.911,123.983 57.009,123.885 57.009,122.578 57.253,122.334 57.655,122.334 57.899,122.578 57.899,123.885 57.996,123.983 58.191,123.983 58.289,123.885 58.289,122.558 58.557,122.289 80.875,99.971 80.875,82.15 84.35,78.675 85.472,78.675 85.482,78.685 86.603,78.685 86.875,78.413 86.875,78.3 87.06,78.115 87.715,78.115 U27.D4@88,78.4
LVDS1.D0con_N: CN2.10 U7.1 | length 6.8
  Top Layer w0.09: CN2.10@51.25,128.5 51.25,128.005 51.125,127.88 51.125,123.45 51.65,122.925 52.217,122.925 52.237,122.945 52.52,122.945 U7.1@52.575,123
LVDS1.D0con_P: CN2.11 U7.2 | length 7.2
  Top Layer w0.09: CN2.11@50.75,128.5 50.75,128.005 50.875,127.88 50.875,123.346 51.071,123.15 51.248,122.973 51.546,122.675 52.217,122.675 52.237,122.655 52.52,122.655 U7.2@52.575,122.6
LVDS1.D1_N: U6.10 U27.D1 | length 69.7
  Top Layer w0.09: U6.10@50.3,122.075 50.245,122.02 50.245,121.737 50.225,121.717 50.225,121.643 50.225,121.2 50.437,120.988 51.736,120.988 51.854,120.987 51.951,121.085 51.951,121.311 52.195,121.555 52.597,121.555 52.841,121.311 52.841,120.864 52.939,120.767 53.134,120.767 53.231,120.864 53.231,121.311 53.475,121.555 53.877,121.555 54.121,121.311 54.121,120.864 54.219,120.767 54.414,120.767 54.511,120.864 54.511,121.311 54.755,121.555 55.157,121.555 55.401,121.311 55.401,120.864 55.499,120.767 55.694,120.767 55.791,120.864 55.791,121.311 56.035,121.555 56.437,121.555 56.681,121.311 56.681,120.864 56.779,120.767 56.974,120.767 57.071,120.864 57.071,121.311 57.315,121.555 57.717,121.555 57.961,121.311 57.961,121.085 58.059,120.987 58.691,120.987 58.794,120.885 80.2,99.479 80.2,81.954 83.789,78.365 85.565,78.365 U27.D1@85.6,78.4
LVDS1.D1_P: U6.9 U27.D2 | length 71.1
  Top Layer w0.09: U6.9@49.9,122.075 49.955,122.02 49.955,121.737 49.975,121.717 49.975,121.539 49.975,121.096 50.334,120.738 51.736,120.738 51.957,120.738 52.201,120.981 52.201,121.208 52.299,121.305 52.494,121.305 52.591,121.208 52.591,120.761 52.835,120.517 53.237,120.517 53.481,120.761 53.481,121.208 53.579,121.305 53.774,121.305 53.871,121.208 53.871,120.761 54.115,120.517 54.517,120.517 54.761,120.761 54.761,121.208 54.859,121.305 55.054,121.305 55.151,121.208 55.151,120.761 55.395,120.517 55.797,120.517 56.041,120.761 56.041,121.208 56.139,121.305 56.334,121.305 56.431,121.208 56.431,120.761 56.675,120.517 57.077,120.517 57.321,120.761 57.321,121.208 57.419,121.305 57.614,121.305 57.711,121.208 57.711,120.981 57.955,120.738 58.588,120.738 58.794,120.531 79.95,99.375 79.95,81.85 83.685,78.115 85.718,78.115 86.003,78.4 U27.D2@86.4,78.4
LVDS1.D1con_N: CN2.12 U6.1 | length 5.5
  Top Layer w0.09: CN2.12@50.25,128.5 50.25,128.005 50.125,127.88 50.125,123.761 50.225,123.661 50.225,123.483 50.245,123.463 50.245,123.18 U6.1@50.3,123.125
LVDS1.D1con_P: CN2.13 U6.2 | length 5.5
  Top Layer w0.09: CN2.13@49.75,128.5 49.75,128.005 49.875,127.88 49.875,123.657 49.975,123.557 49.975,123.483 49.955,123.463 49.955,123.18 U6.2@49.9,123.125
LVDS1.D2_N: U6.7 U27.E4 | length 68.6
  Top Layer w0.09: U6.7@49.1,122.075 49.045,122.02 49.045,121.737 49.025,121.717 49.025,121.643 49.025,120.304 49.279,120.05 58.325,120.05 79.275,99.1 79.275,81.754 81.349,79.679 81.349,79.669 83.083,77.935 87.665,77.935 U27.E4@88,77.6
LVDS1.D2_P: U6.6 U27.E3 | length 68.1
  Top Layer w0.09: U6.6@48.7,122.075 48.755,122.02 48.755,121.737 48.775,121.717 48.775,121.539 48.775,120.2 49.175,119.8 58.221,119.8 79.025,98.996 79.025,81.65 81.172,79.503 81.183,79.503 82.986,77.7 87.043,77.7 87.143,77.6 U27.E3@87.2,77.6
LVDS1.D2con_N: CN2.14 U6.4 | length 5.5
  Top Layer w0.09: U6.4@49.1,123.125 49.045,123.18 49.045,123.463 49.025,123.483 49.025,123.557 49.125,123.657 49.125,127.88 49.25,128.005 CN2.14@49.25,128.5
LVDS1.D2con_P: CN2.15 U6.5 | length 5.5
  Top Layer w0.09: U6.5@48.7,123.125 48.755,123.18 48.755,123.463 48.775,123.483 48.775,123.661 48.875,123.761 48.875,127.88 48.75,128.005 CN2.15@48.75,128.5
LVDS1.D3_N: U5.7 U27.F3 | length 71.8
  Top Layer w0.09: U5.7@45.5,122.075 45.445,122.02 45.445,121.737 45.425,121.717 45.425,121.517 45.425,119.7 47,118.125 57.6,118.125 77.35,98.375 77.35,81.5 81.76,77.09 86.513,77.09 86.803,76.8 U27.F3@87.2,76.8
LVDS1.D3_P: U5.6 U27.F2 | length 71.3
  Top Layer w0.09: U5.6@45.1,122.075 45.155,122.02 45.155,121.737 45.175,121.717 45.175,121.413 45.175,119.596 46.896,117.875 57.496,117.875 77.1,98.271 77.1,81.396 81.614,76.882 86.261,76.882 86.343,76.8 U27.F2@86.4,76.8
LVDS1.D3con_N: CN2.18 U5.4 | length 6.2
  Top Layer w0.09: U5.4@45.5,123.125 45.445,123.18 45.445,123.463 45.425,123.483 45.425,123.557 45.425,124.013 47.125,125.713 47.125,127.88 47.25,128.005 CN2.18@47.25,128.5
LVDS1.D3con_P: CN2.19 U5.5 | length 6.2
  Top Layer w0.09: U5.5@45.1,123.125 45.155,123.18 45.155,123.463 45.175,123.483 45.175,123.661 45.175,124.116 46.875,125.816 46.875,127.88 46.75,128.005 CN2.19@46.75,128.5
LVDS.RESET: CN2.6 R1.2 R2.2 U3.1 | length 4
  Top Layer w0.2: CN2.6@53.25,128.5 U3.1@53.25,126.45 R1.2@53.25,125.645 R2.2@54.35,125.645
mkB.AN: U27.V5 U53.3 U53.4 | length 45.4
  Top Layer w0.09: v2(88.471,67.58) 88.471,67.555 88.8,67.225 U27.V5@88.8,67.2
  Top Layer w0.3: v1@53.362,59.687 U53.4@53.362,60.838 U53.3@53.362,63.038
  Signal Layer 2 w0.1: v1(53.35,59.675) 54.375,60.7 79.225,60.7 80.6,62.075 87.75,62.075 88.525,62.85 88.525,66.3 88.925,66.7 88.925,67.125 v2(88.471,67.58)
mkB.CS: CN25.3 U27.R6 | length 42.5
  Top Layer w0.1: v2(89.2,69.2) U27.R6@89.6,69.6
  Signal Layer 2 w0.1: v1(62.325,69.25) 63.267,70.192 64.45,70.192 65.133,70.875 86.519,70.875 87.819,69.575 88.825,69.575 v2(89.2,69.2)
  Bottom Layer w0.1: CN25.3@61.055,57.96 62.91,57.96 63.275,58.325 63.275,68.3 v1(62.325,69.25)
mkB.INT: CN25.15 U27.N3 | length 57.6
  Top Layer w0.09: 81.172,71.64 83.877,71.64 83.982,71.535 86.75,71.535 87.045,71.24 87.16,71.24 U27.N3@87.2,71.2
  Top Layer w0.1: v1(37.31,60.495) 46.995,60.495 57.925,71.425 58.85,71.425 59.075,71.2 61.567,71.2 62.042,71.675 62.658,71.675 62.933,71.4 67.9,71.4 68.725,72.225 69.273,72.225 69.858,71.64 81.172,71.64
  Bottom Layer w0.4: CN25.15@35.295,60.5 v1@37.305,60.5
mkB.MISO: CN25.5 U27.N6 | length 48.9
  Top Layer w0.1: v2(89.2,70.8) U27.N6@89.6,71.2
  Signal Layer 2 w0.1: v1(62.3,70.825) 63.075,70.825 63.508,70.392 64.367,70.392 65.05,71.075 86.594,71.075 86.869,70.8 v2(89.2,70.8)
  Bottom Layer w0.1: CN25.5@61.055,52.88 63.23,52.88 63.675,53.325 63.675,69.45 v1(62.3,70.825)
mkB.MOSI: CN25.6 U27.N5 | length 48.4
  Top Layer w0.09: 81.172,71.2 81.652,71.2 81.712,71.26 83.748,71.26 83.833,71.175 86.551,71.175 87.031,70.695 88.295,70.695 U27.N5@88.8,71.2
  Top Layer w0.1: v1(63.975,70.825) 64.35,71.2 81.172,71.2
  Bottom Layer w0.1: CN25.6@61.055,50.34 63.265,50.34 63.875,50.95 63.875,70.125 63.975,70.225 v1(63.975,70.825)
mkB.PWM: CN25.16 U27.AB4 | length 54.3
  Top Layer w0.1: v2(87.475,63.05) 88,63.575 U27.AB4@88,64
  Signal Layer 2 w0.1: v1(37.31,63.035) 37.745,62.6 54.875,62.6 55.6,61.875 67.35,61.875 68.525,63.05 v2(87.475,63.05)
  Bottom Layer w0.4: CN25.16@35.295,63.04 v1@37.305,63.04
mkB.RST: CN25.2 U27.P5 | length 37.9
  Top Layer w0.09: 83.395,70.522 83.453,70.522 83.53,70.445 85.689,70.445 86.059,70.075 86.597,70.075 86.777,69.895 87.623,69.895 87.828,70.1 ; 88.125,70.1 88.405,70.38 88.78,70.38 U27.P5@88.8,70.4
  Top Layer w0.1: v1(62.325,68.45) 63.35,69.475 64.075,69.475 65,70.4 81.905,70.4 82.027,70.522 83.395,70.522 ; 87.828,70.1 88.125,70.1
  Bottom Layer w0.1: CN25.2@61.055,60.5 62.7,60.5 63.075,60.875 63.075,67.7 v1(62.325,68.45)
mkB.RX: CN25.14 U27.P3 | length 67.3
  Top Layer w0.09: 81.172,71 81.706,71 81.786,71.08 83.673,71.08 83.758,70.995 86.477,70.995 87.032,70.44 87.16,70.44 U27.P3@87.2,70.4
  Top Layer w0.1: v1(58.6,71) 61.65,71 62.125,71.475 62.575,71.475 63.65,70.4 64.151,70.4 64.751,71 81.172,71
  Signal Layer 2 w0.1: v1(37.025,69.65) 37.057,69.618 45.267,69.618 45.274,69.625 45.9,69.625 46.65,68.875 50.441,68.875 51.041,69.475 55.975,69.475 57.5,71 v1(58.6,71)
  Bottom Layer w0.1: CN25.14@35.295,57.96 37.36,57.96 38.3,58.9 38.3,63.9 37.025,65.175 v1(37.025,69.65)
mkB.SCK: CN25.4 U27.P4 | length 44
  Top Layer w0.09: 81.863,70.895 83.604,70.895 83.694,70.805 86.412,70.805 86.695,70.522 86.695,70.28 86.9,70.075 87.45,70.075 87.775,70.4 U27.P4@88,70.4
  Top Layer w0.1: v1(62.325,70.1) 64.134,70.1 64.834,70.8 81.768,70.8 81.863,70.895
  Bottom Layer w0.1: CN25.4@61.055,55.42 63.07,55.42 63.475,55.825 63.475,68.95 v1(62.325,70.1)
mkB.TX: CN25.13 U27.P2 | length 67.1
  Top Layer w0.09: 81.862,70.625 81.869,70.625 81.951,70.707 83.537,70.707 83.619,70.625 86.175,70.625 U27.P2@86.4,70.4
  Top Layer w0.1: v1(57.925,70.55) 61.175,70.55 62.05,69.675 63.992,69.675 64.917,70.6 81.837,70.6 81.862,70.625
  Signal Layer 2 w0.1: v1(37.825,68.7) 37.85,68.675 50.524,68.675 51.124,69.275 56.058,69.275 57.333,70.55 v1(57.925,70.55)
  Bottom Layer w0.1: CN25.13@35.295,55.42 37.545,55.42 39.275,57.15 39.275,64.05 37.825,65.5 v1(37.825,68.7)
NetB2_3: B2.3 B2.4 C5.2 U26.1 | length 77.7
  Top Layer w0.1: B2.3@23.073,120.45 B2.4@31.023,120.45 C5.2@32.675,120.45 v1(35.8,120.45)
  Top Layer w0.15: v1(43.025,70.2) 43.475,70.65 43.475,73.629 44.162,74.316 44.162,75.064 44.555,75.457 U26.1@45.1,75.457
  Bottom Layer w0.1: v1(35.8,120.45) 35.8,105.05 34.35,103.6 34.35,91 40.125,85.225 43.95,85.225 45.275,83.9 45.275,75.625 43.025,73.375 v1(43.025,70.2)
NetB3_3: B3.3 B3.4 R26.1 | length 10
  Top Layer w0.2: R26.1@2.5,116.738 2.5,115.113 B3.4@2.812,114.8 B3.3@10.763,114.8
NetB4_3: B4.3 B4.4 CN7.1 R24.2 R28.2 U19.1 | length 17
  Top Layer w0.2: R28.2@15.813,106.725 R24.2@15.813,107.675 15.813,108.725 B4.3@15.812,110.3 B4.4@23.763,110.3 23.763,107.85 22.863,106.95 CN7.1@21.083,106.95
NetB5_3: B5.3 B5.4 CN8.1 R25.2 R29.2 U20.1 | length 17
  Top Layer w0.2: R29.2@28.813,106.725 R25.2@28.813,107.675 28.813,108.725 B5.3@28.813,110.3 B5.4@36.763,110.3 36.763,107.85 35.863,106.95 CN8.1@34.083,106.95
NetC43_1: C43.1 R52.1 U26.45 | length 7.6
  Top Layer w0.21: 43.975,80.427 U26.45@44.53,80.427
  Top Layer w0.25: R52.1@38.175,80.575 38.185,80.565 C43.1@38.185,79.627 ; C43.1@38.215,79.617 40.931,79.617 41.376,80.062 41.651,80.062 42.016,80.427 43.975,80.427
NetC66_2: C66.2 R58.1 U26.14 | length 8.5
  Top Layer w0.21: U26.14@50.3,75.457 50.81,75.457 51.348,74.919 51.588,74.919 51.945,74.561 51.945,73.429 52.445,72.929 C66.2@52.445,72.377
  Top Layer w0.3: R58.1@52.15,68.675 52.15,69.989 51.8,70.339 51.8,71.732 52.27,72.202 52.27,72.22 52.427,72.377 C66.2@52.445,72.377
NetC70_2: C70.2 R56.2 R57.2 U26.3 | length 10.4
  Top Layer w0.21: 45.673,74.425 45.9,74.652 U26.3@45.9,75.457
  Top Layer w0.3: C70.2@44.675,72.002 44.7,72.002 v3@45.285,72.002
  Top Layer w0.4: R57.2@43.225,69.202 R56.2@44.45,69.202 45.448,69.202 v1(45.45,69.2) ; C70.2@44.7,72.002 44.714,72.016 44.714,72.512 45.16,72.958 45.16,73.912 45.673,74.425
  Bottom Layer w0.3: v3(45.31,72.002) 45.723,72.002 46.075,71.65 46.075,69.825 v1(45.45,69.2)
NetC71_2: C71.2 U26.12 | length 4.9
  Top Layer w0.21: U26.12@49.5,75.457 49.5,74.843 49.671,74.672
  Top Layer w0.3: 49.671,74.672 50.225,74.118 50.225,73.001 51.05,72.176 C71.2@51.05,71.227
NetC75_1: C75.1 U26.8 | length 5.4
  Top Layer w0.21: U26.8@47.9,75.457 47.9,73.961 48.325,73.536 48.325,73.172 48.498,73
  Top Layer w0.3: 48.498,73 49,72.497 49,71.67 48.875,71.545 C75.1@48.875,70.532
NetC76_2: C76.2 R55.2 U30.1 U30.6 | length 7.1
  Top Layer w0.2: U30.1@151.855,67.825 151.855,68.65 152.305,69.1 154.455,69.1
  Top Layer w0.5: U30.6@154.455,67.825 154.455,69.1 R55.2@154.455,71.3
NetC81_1: C81.1 R64.2 X1.1 | length 2.2
  Top Layer w0.1: X1.1@76.525,67.4 78.65,67.4 R64.2@78.7,67.45
NetC88_2: C88.2 D6.2 R66.2 | length 8
  Top Layer w0.3: C88.2@67.475,60.4 67.475,59.726 67.651,59.55 68.675,59.55 ; R66.2@68.675,60.395 68.675,59.55 ; D6.2@70.625,63.075 70.625,60.025 70.15,59.55 68.675,59.55
NetC89_2: C89.2 R65.2 R69.1 U30.4 | length 4
  Top Layer w0.2: U30.4@154.455,65.925 R65.2@155.455,65.925
  Top Layer w0.5: R69.1@154.455,62.875 C89.2@154.455,64.225 U30.4@154.455,65.925
NetC91_2: C91.2 R70.2 X2.4 | length 2
  Top Layer w0.1: R70.2@73.575,61.575 C91.2@74.55,61.575 X2.4@75.548,61.576 X2.4@75.548,61.576
NetC92_1: C92.1 R74.1 R75.1 X2.1 | length 2.9
  Top Layer w0.09: C92.1@74.55,60.775 X2.1@75.548,60.776 X2.1@75.548,60.776 75.548,59.852 R74.1@75.55,59.85 76.35,59.85 R75.1@76.475,59.725
NetC101_2: C101.2 C102.2 R92.2 U33.12 U33.13 | length 4.2
  Top Layer w0.2: R92.2@102.55,46.29 C101.2@103.525,46.29 C102.2@104.425,46.29 ; U33.13@105.375,45.79 104.525,45.79 104.425,45.89 C102.2@104.425,46.29 ; U33.12@105.375,46.29 C102.2@104.425,46.29
NetC110_2: C110.2 D2.2 D3.2 U35.3 U35.5 | length 8.9
  Top Layer w0.15: U35.5@29.37,30.325 29.37,30.925 30.67,32.225 U35.3@31.57,32.225
  Top Layer w0.6: U35.3@31.57,32.225 31.57,34.3 D2.2@31.57,37.825
NetC114_2: C114.2 C118.2 C151.1 JP4.3 L8.2 R208.1 | length 16.1
  Top Layer w0.2: R208.1@15.925,22.2 C151.1@15.925,21.225 16.75,21.225 17.35,21.825 17.35,23.663 17.467,23.78 JP4.3@19.725,23.78
  Top Layer w0.8: 8.125,30.675 C118.2@8.125,31.625 C114.2@8.125,33.65 8.125,34.95
  Top Layer w1: C118.2@8.125,31.625 9.425,31.625 9.8,32 9.8,32.1 L8.2@9.775,32.125 9.775,33.275 9.4,33.65 C114.2@8.125,33.65
NetC115_2: C115.2 U34.32 X3.3 | length 5
  Top Layer w0.1: X3.3@120.555,32.125 120.555,32.075 121.18,31.45 122.18,31.45 122.23,31.5 C115.2@122.625,31.5 U34.32@125.25,31.5
NetC116_2: C116.2 C117.2 C127.1 C130.2 C148.2 F1.2 U37.1 U37.2 U37.6 | length 9.3
  Top Layer w0.4: C148.2@13.325,22.6 13.325,23.725 U37.1@13.325,24.6 ; C148.2@13.875,22.6 14.125,22.85 U37.2@14.125,24.6
  Top Layer w0.5: v1(11.925,22.6) v1(12.625,22.6) ; U37.6@14.925,28.4 14.925,29.05 v1(15.375,29.5) v1(16.075,29.5) v1(16.775,29.5) v1(17.475,29.5)
  Top Layer w0.55: v1(12.625,22.6) 13.325,22.6 C148.2@13.725,22.6
  other v1: 12.625,21.95 12.625,23.25
NetC119_2: C119.2 U34.14 | length 1.8
  Top Layer w0.2: U34.14@130.75,31.5 131.811,31.5 C119.2@132.311,32
NetC126_2: C126.2 U34.33 X3.1 | length 3.8
  Top Layer w0.1: X3.1@121.605,30.775 121.68,30.7 C126.2@122.625,30.7 123.2,30.7 123.5,31 U34.33@125.25,31
NetC128_2: C128.2 U34.34 | length 3.1
  Top Layer w0.2: C128.2@123.2,28.9 123.2,29.545 124.155,30.5 U34.34@125.25,30.5
NetC131_2: C131.2 R181.2 TP33.1 | length 2.8
  Top Layer w0.2: R181.2@46.925,26.125 TP33.1@48.45,26.125 C131.2@48.45,27.4
NetC132_2: C132.2 U36.F13 | length 3.5
  Top Layer w0.12: U36.F13@42.925,26.125 43.225,26.425 44.775,26.425 45.475,27.125 C132.2@46.025,27.125
NetC134_2: C134.2 R182.1 X4.1 | length 4.3
  Top Layer w0.15: X4.1@52.025,26.525 52.534,26.016 52.534,25.716 52.8,25.45 C134.2@54.85,25.45 55.5,25.45 R182.1@55.625,25.575
NetC135_2: C135.2 R183.1 X5.1 | length 4.3
  Top Layer w0.15: X5.1@77.025,26.525 77.534,26.016 77.534,25.716 77.8,25.45 C135.2@79.85,25.45 80.5,25.45 R183.1@80.625,25.575
NetC136_2: C136.2 R184.1 X6.1 | length 4.3
  Top Layer w0.15: X6.1@102.025,26.525 102.534,26.016 102.534,25.716 102.8,25.45 C136.2@104.85,25.45 105.5,25.45 R184.1@105.625,25.575
NetC137_2: C137.2 R188.1 X4.3 | length 2.2
  Top Layer w0.15: X4.3@53.625,24.325 54,24.7 C137.2@54.85,24.7 55.5,24.7 R188.1@55.625,24.575
NetC138_2: C138.2 R189.1 X5.3 | length 2.2
  Top Layer w0.15: X5.3@78.625,24.325 79,24.7 C138.2@79.85,24.7 80.5,24.7 R189.1@80.625,24.575
NetC139_2: C139.2 R190.1 X6.3 | length 2.2
  Top Layer w0.15: X6.3@103.625,24.325 104,24.7 C139.2@104.85,24.7 105.5,24.7 R190.1@105.625,24.575
NetC145_2: C145.2 U36.J14 | length 2.9
  Top Layer w0.12: U36.J14@43.575,24.175 43.875,23.875 44.75,23.875 45.5,23.125 C145.2@46.025,23.125
NetC150_2: C150.2 C155.2 CN19.T1 U41.7 U44.1 | length 12.5
  Top Layer w1: U41.7@130.43,19.4 130.43,18.136 131.016,17.55 132.37,17.55 132.87,18.05 133.95,18.05 C150.2@134.15,18.25 136.025,18.25 U44.1@137.5,18.25 ; CN19.T1@137.5,14.62 U44.1@137.5,18.25 ; U44.1@137.5,18.275 U44.1@137.5,18.25
NetC151_2: C151.2 R204.2 R208.2 U37.3 | length 3.4
  Top Layer w0.4: U37.3@14.925,24.6 14.925,23.445 15.025,23.345 R204.2@15.025,23.25 R208.2@15.025,22.2 C151.2@15.025,21.225
NetC152_2: C152.2 CN16.5 CN16.6 | length 6
  Top Layer w0.5: C152.2@61.365,19.175 CN16.5@61.365,16.29 61.365,15.02 CN16.6@62.635,13.75
NetC153_2: C153.2 CN17.5 CN17.6 | length 6
  Top Layer w0.5: C153.2@86.365,19.175 CN17.5@86.365,16.29 86.365,15.02 CN17.6@87.635,13.75
NetC154_2: C154.2 CN18.5 CN18.6 | length 6
  Top Layer w0.5: C154.2@111.365,19.175 CN18.5@111.365,16.29 111.365,15.02 CN18.6@112.635,13.75
NetC160_2: C160.2 U36.M10 | length 7.6
  Top Layer w0.12: U36.M10@40.975,22.225 40.625,22.575 39.6,22.575 39.35,22.325 39.35,20.075 39.8,19.625 41.075,19.625 41.6,19.1 C160.2@41.6,18.3
NetC161_2: C161.2 C163.2 CN19.B1 U41.6 U51.1 | length 14.9
  Top Layer w1: U41.6@129.16,19.4 129.16,17.19 130.245,16.105 130.245,15.915 C161.2@130.445,15.715 130.445,13.626 U51.1@130.445,12.025 ; U51.1@130.47,12 CN19.B1@137.5,12
NetC168_2: C168.2 CN15.A5 U50.15 | length 25.1
  Top Layer w0.1: v1(156.71,19.25) 156.71,21.085 157.597,21.972 160.878,21.972 161.325,21.525 CN15.A5@162.7,21.525
  Top Layer w0.2: U50.15@162.65,9.125 v1(163.95,9.125) C168.2@164.625,9.125
  Bottom Layer w0.2: v1(156.71,19.25) 156.71,19.235 161.275,14.67 163.696,14.67 163.9,14.466 163.9,12.316 163.6,12.016 163.6,9.475 v1(163.95,9.125)
NetC170_2: C170.2 U50.14 | length 1.6
  Top Layer w0.2: U50.14@162.15,9.125 162.15,8.395 C170.2@162.8,7.745
NetC171_2: C171.2 CN15.B5 U50.13 | length 22.4
  Top Layer w0.1: v5(163.74,22.775) CN15.B5@164.4,22.775
  Top Layer w0.2: C171.2@161.65,7.3 v1(161.65,7.975) U50.13@161.65,9.125
  Bottom Layer w0.2: v1(161.65,7.975) 163.7,7.975 164.425,8.7 164.425,9.425 163.9,9.95 163.9,11.747 164.2,12.047 164.2,16.075 162.575,17.7 162.575,18.975 164.75,21.15 164.75,22.508 164.483,22.775 v5(163.74,22.775)
NetC173_2: C173.2 U52.1 | length 1.9
  Top Layer w0.2: U52.1@32.625,4.65 32.625,4.192 32.742,4.075 C173.2@34.025,4.075
NetC181_2: C181.2 C182.2 U24.C2 | length 3
  Top Layer w0.09: U24.C2@108.275,87.85 108.525,87.6 v1(108.525,86.8)
  Bottom Layer w0.2: C181.2@106.7,86.8 C182.2@107.825,86.8 v1(108.525,86.8)
NetC225_2: C225.2 U27.M8 | length 1.4
  Top Layer w0.2: v2(90.8,72.4) U27.M8@91.2,72
  Bottom Layer w0.2: C225.2@90.3,71.8 90.3,71.85 90.8,72.35 v2(90.8,72.4)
